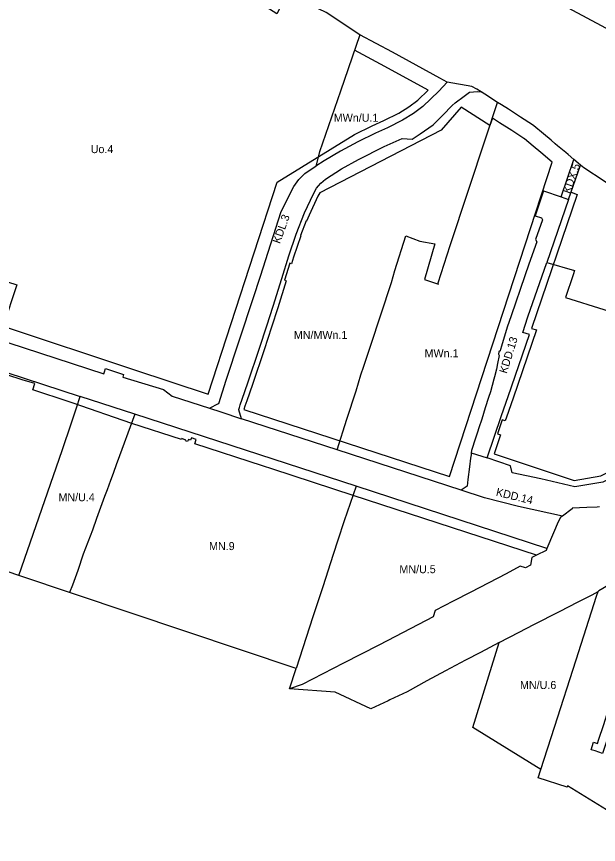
# Model space of a CAD drawing. Extents: x 7416797 to 7419013, y 5549660 to 5551534.
# Drawn here: x 7417878 to 7418242, y 5549927 to 5550444 of the extents above; entities that cross this region are included whole.
import ezdxf

# ---------------------------------------------------------------- set-up
doc = ezdxf.new("R2010")
doc.units = 0
for name, color, linetype in [('LIN_Linia Zabudowy Nieprzekraczalna', 7, 'Continuous'), ('LIN_linie_rozgraniczajace', 7, 'Continuous'), ('TXT_Oznaczenia_przeznaczen', 7, 'Continuous')]:
    doc.layers.add(name, color=color, linetype=linetype)

msp = doc.modelspace()

# ---------------------------------------------------------------- linework, layer by layer
at = {"layer": 'LIN_Linia Zabudowy Nieprzekraczalna'}
msp.add_line((7418173.82, 5550375.74), (7418155.85, 5550387.25), dxfattribs=at)
for points in [[(7417840.12, 5550288.54), (7417878.46, 5550276.31), (7417869.88, 5550250.33), (7417951.32, 5550223.45), (7417997.93, 5550208.07), (7418041.12, 5550340.32), (7418089.34, 5550370.12), (7418100.28, 5550375.53), (7418107.68, 5550378.78), (7418116.88, 5550383.37), (7418123.2, 5550387.43), (7418128.8, 5550391.54), (7418135.37, 5550397.89), (7418108.17, 5550412.67), (7418089.38, 5550422.85)], [(7418155.85, 5550387.25), (7418143.37, 5550372.91), (7418067.56, 5550333.64), (7418066.5, 5550331.51), (7418060.9, 5550319.78), (7418059.42, 5550316.03), (7418059.04, 5550316.17), (7418055.57, 5550306.95), (7418055.82, 5550306.86), (7418051.29, 5550293.44), (7418050.02, 5550289.37), (7418048.88, 5550289.73), (7418045.51, 5550279.16), (7418046.72, 5550278.77), (7418041.43, 5550261.95), (7418037.57, 5550249.74), (7418032.89, 5550235.73), (7418025.56, 5550214), (7418022.12, 5550203.89), (7418020.92, 5550200.38), (7418020.3, 5550198.47), (7418148.65, 5550156.5), (7418212.68, 5550352.85)], [(7418212.68, 5550352.85), (7418205.54, 5550358.86), (7418200.77, 5550362.87), (7418195.35, 5550367.43), (7418195.01, 5550367.64), (7418187.44, 5550372.56), (7418179.91, 5550377.45), (7418175.37, 5550380.38), (7418173.82, 5550375.74)], [(7418224.51, 5550334.02), (7418228.27, 5550332.74), (7418199.84, 5550249.04), (7418202.92, 5550248.15), (7418188.27, 5550205.44), (7418184.09, 5550193.56), (7418183.3, 5550191.24), (7418181.39, 5550191.86), (7418178.51, 5550183.17), (7418180.35, 5550182.52), (7418176.38, 5550170.79)], [(7418176.38, 5550170.79), (7418226.4, 5550154.02), (7418242.97, 5550156.96), (7418327.21, 5550199.31), (7418361.69, 5550210.89), (7418382.5, 5550273.76)], [(7418202.86, 5550107.48), (7418088.49, 5550144.72), (7418038.24, 5550161.14), (7418031.79, 5550163.31), (7417989.56, 5550177), (7417990.47, 5550179.64), (7417987.45, 5550180.72), (7417986.89, 5550179.22), (7417985.65, 5550179.68), (7417985.14, 5550178.4), (7417983.81, 5550178.86), (7417983.97, 5550179.27), (7417981.48, 5550180.23), (7417981.26, 5550179.68), (7417950.32, 5550189.71), (7417913.08, 5550202.54), (7417904.24, 5550205.44), (7417895.44, 5550208.37), (7417888.52, 5550210.72), (7417889.7, 5550214.55), (7417881.87, 5550216.96), (7417872.29, 5550220.12), (7417870.86, 5550215.59), (7417858.1, 5550219.74)]]:
    msp.add_lwpolyline(points, dxfattribs=at)
at = {"layer": 'LIN_linie_rozgraniczajace'}
for p, q in [((7418218.23, 5550331.16), (7418226.3, 5550354.48)), ((7418059.79, 5550346.72), (7418065.2, 5550350.32)), ((7418222.96, 5550329.55), (7418230.4, 5550351.03)), ((7417952.19, 5550195.41), (7417917.95, 5550206.56)), ((7418090.35, 5550150.42), (7417952.19, 5550195.41)), ((7418155.91, 5550148), (7418078.49, 5550173.21)), ((7418162.19, 5550171.4), (7418172.05, 5550168.19)), ((7418209.39, 5550111.66), (7418090.35, 5550150.42))]:
    msp.add_line(p, q, dxfattribs=at)
for points in [[(7418092.7, 5550432.42), (7418071.51, 5550446.22), (7418057.57, 5550452.93), (7418047.73, 5550458.5), (7418040.72, 5550445.49), (7417999.52, 5550471.94), (7418014.05, 5550489.79), (7417968.97, 5550532.54), (7417954.56, 5550547.11), (7417895.48, 5550596.2), (7417893.88, 5550597.78), (7417876.89, 5550604.46), (7417876.86, 5550604.47), (7417873.74, 5550605.53)], [(7418216.45, 5550452.52), (7418293.85, 5550411.16), (7418364.15, 5550380.58), (7418425.56, 5550356.68), (7418460.75, 5550342.97), (7418587.07, 5550302.96), (7418652.56, 5550283.78)], [(7418092.7, 5550432.42), (7418080.49, 5550397.2), (7418067.44, 5550359.23), (7418065.2, 5550350.32)], [(7418147.15, 5550402.87), (7418142.55, 5550405.37), (7418112.94, 5550421.46), (7418092.7, 5550432.42)], [(7418147.15, 5550402.87), (7418141.87, 5550397.2), (7418132.03, 5550387.7), (7418126.03, 5550383.31), (7418119.36, 5550379.02), (7418109.8, 5550374.25), (7418102.39, 5550371), (7418091.42, 5550365.57), (7418080.6, 5550359.71), (7418070.38, 5550353.75), (7418065.2, 5550350.32)], [(7418168.42, 5550396.8), (7418165.58, 5550398.4), (7418162.53, 5550400.12), (7418147.15, 5550402.87)], [(7418018.75, 5550192.67), (7418017.04, 5550198.21), (7418017.01, 5550198.3), (7418017.46, 5550199.73), (7418018, 5550201.39), (7418019.21, 5550204.93), (7418022.65, 5550215.03), (7418029.98, 5550236.75), (7418034.64, 5550250.72), (7418038.49, 5550262.9), (7418043.96, 5550280.27), (7418048.36, 5550294.42), (7418052.93, 5550307.94), (7418058.1, 5550321.13), (7418063.78, 5550333), (7418065.57, 5550336.6), (7418066.77, 5550337.99), (7418068.19, 5550339.65), (7418071.15, 5550342.31), (7418081.09, 5550348.65), (7418091.81, 5550354.49), (7418107.91, 5550362.61), (7418119.15, 5550367.58), (7418125.34, 5550367.29), (7418130.38, 5550370.57), (7418138.38, 5550376.16), (7418144.35, 5550382.16), (7418150.36, 5550388.29), (7418152.05, 5550389.93), (7418157.65, 5550394.05), (7418161.1, 5550396.59), (7418166.07, 5550396.95), (7418168.42, 5550396.8)], [(7418178.64, 5550390.18), (7418170.66, 5550395.35), (7418168.42, 5550396.8)], [(7418078.49, 5550173.21), (7418084.51, 5550192.3), (7418090.24, 5550210.04), (7418093.25, 5550219.94), (7418095.11, 5550225.49), (7418099.22, 5550237.97), (7418112.37, 5550277.66), (7418114.48, 5550285.19), (7418121.37, 5550306.79), (7418130.13, 5550303.54), (7418139.46, 5550301.81), (7418132.9, 5550279.6), (7418141.64, 5550276.56), (7418141.42, 5550277.44), (7418149.01, 5550300.79), (7418171.47, 5550368.72), (7418178.64, 5550390.18)], [(7418226.3, 5550354.48), (7418222.58, 5550357.61), (7418221.15, 5550358.81), (7418217.06, 5550362.24), (7418216.03, 5550363.11), (7418214.61, 5550364.3), (7418211.97, 5550366.52), (7418207.2, 5550370.52), (7418201.29, 5550375.5), (7418200.43, 5550376.05), (7418192.88, 5550380.95), (7418185.34, 5550385.84), (7418180.96, 5550388.67), (7418178.64, 5550390.18)], [(7418230.4, 5550351.03), (7418226.3, 5550354.48)], [(7418392.15, 5550266.3), (7418392.28, 5550269.21), (7418382.5, 5550273.76), (7418363.87, 5550282.44), (7418355.95, 5550286.12), (7418348.45, 5550289.62), (7418339.49, 5550293.79), (7418331.21, 5550297.64), (7418322.84, 5550301.53), (7418313.92, 5550305.69), (7418312.96, 5550306.14), (7418304.3, 5550310.28), (7418302.75, 5550310.89), (7418295.33, 5550314.34), (7418285.69, 5550318.83), (7418283.2, 5550319.99), (7418270, 5550326.12), (7418261.14, 5550330.25), (7418253.52, 5550335.3), (7418245.06, 5550340.92), (7418232.56, 5550349.21), (7418230.4, 5550351.03)], [(7418050.59, 5550336.14), (7418051.44, 5550337.68), (7418052.4, 5550339.17), (7418053.44, 5550340.6), (7418054.56, 5550341.98), (7418055.77, 5550343.28), (7418057.05, 5550344.51), (7418058.39, 5550345.66), (7418059.79, 5550346.72)], [(7417998.7, 5550199.2), (7418004.43, 5550202.1), (7418004.55, 5550202.17), (7418009.28, 5550216.79), (7418025.97, 5550267.77), (7418030.52, 5550281.68), (7418043.5, 5550321.94), (7418050.34, 5550335.66)], [(7418050.34, 5550335.66), (7418050.59, 5550336.14)], [(7418207.37, 5550334.88), (7418202.02, 5550319.37), (7418205.94, 5550318.02), (7418206.56, 5550316.75), (7418202.34, 5550304.54), (7418203.02, 5550303.14), (7418198.18, 5550289.11), (7418195.7, 5550281.91), (7418187.07, 5550256.91), (7418184.62, 5550249.82), (7418181.01, 5550237.9), (7418180.48, 5550235.79), (7418180.29, 5550235.04), (7418179.46, 5550234.47), (7418179.11, 5550233.01), (7418179.63, 5550232.17), (7418178.6, 5550227.15), (7418177.94, 5550223.49), (7418176.66, 5550218.83), (7418176.27, 5550217.43), (7418174.09, 5550209.53), (7418173.04, 5550205.95), (7418170.92, 5550199.35), (7418168.68, 5550192.38), (7418166.9, 5550186.86), (7418166.07, 5550184.29), (7418164.43, 5550179.16), (7418162.74, 5550173.94), (7418162.35, 5550172.72), (7418162.19, 5550171.4)], [(7418207.37, 5550334.88), (7418218.23, 5550331.16)], [(7418222.96, 5550329.55), (7418209.31, 5550290.14)], [(7418218.23, 5550331.16), (7418222.96, 5550329.55)], [(7418172.05, 5550168.19), (7418181.01, 5550194.66), (7418185.19, 5550206.55), (7418198.48, 5550245.27), (7418194.31, 5550246.48), (7418197.6, 5550256.33), (7418209.31, 5550290.14)], [(7418209.31, 5550290.14), (7418226.55, 5550285.12), (7418225.73, 5550282.58), (7418221.11, 5550268.3), (7418292.87, 5550245.8), (7418320.28, 5550237.08), (7418377.67, 5550219.01)], [(7417773.52, 5550271.33), (7417853.01, 5550246.64), (7417932.88, 5550220.63), (7417933.29, 5550221.97), (7417933.89, 5550223.94), (7417945.13, 5550220.23), (7417944.62, 5550218.54), (7417969.99, 5550210.96), (7417975.48, 5550206.76), (7417998.7, 5550199.2)], [(7417859.9, 5550225.47), (7417917.95, 5550206.56)], [(7418375.43, 5550212.39), (7418360.4, 5550206.99), (7418328.79, 5550195.63), (7418244.25, 5550153.12), (7418226.9, 5550150.05), (7418205.6, 5550155.1), (7418187.63, 5550158.95), (7418186.67, 5550163.27), (7418172.05, 5550168.19)], [(7417879.77, 5550094.76), (7417906.89, 5550172.8), (7417912.64, 5550190.06), (7417915.74, 5550199.52), (7417917.95, 5550206.56)], [(7417998.7, 5550199.2), (7418005.83, 5550196.87), (7418018.75, 5550192.67)], [(7417952.19, 5550195.41), (7417941.12, 5550165.41), (7417940.75, 5550164.37), (7417938.62, 5550158.44), (7417937.07, 5550154.12), (7417934.97, 5550148.2), (7417933.33, 5550144.07), (7417928.22, 5550130.23), (7417925.67, 5550123.07), (7417919.84, 5550108.08), (7417916.55, 5550097.85), (7417913.21, 5550088.79), (7417911.47, 5550084.11)], [(7418078.49, 5550173.21), (7418018.75, 5550192.67)], [(7418162.19, 5550171.4), (7418162.02, 5550170.08), (7418161.77, 5550168.09), (7418161.09, 5550162.68), (7418160.08, 5550154.61), (7418159.55, 5550150.42), (7418155.91, 5550148)], [(7418281.81, 5549926.8), (7418222.22, 5549963.42), (7418221.96, 5549962.64), (7418204.05, 5549968.49), (7418205.7, 5549973.58), (7418163.13, 5549999.74), (7418179.57, 5550052.94), (7418167.86, 5550046.74), (7418158.62, 5550041.83), (7418146.2, 5550035.24), (7418134.45, 5550029.01), (7418122.22, 5550022.14), (7418111.37, 5550017.01), (7418110.37, 5550016.54), (7418099.58, 5550011.42), (7418077.2, 5550021.94), (7418048.77, 5550023.87), (7418052.9, 5550036.6), (7417879.77, 5550094.76), (7417692.43, 5550159.1)], [(7418090.35, 5550150.42), (7418082.88, 5550128.81), (7418078.84, 5550116.74), (7418076.07, 5550107.78), (7418069.59, 5550087.61), (7418063.38, 5550068.95), (7418052.9, 5550036.6)], [(7418219.12, 5550131.83), (7418191.75, 5550137.91), (7418170.41, 5550143.28), (7418155.91, 5550148)], [(7418242.31, 5550137.6), (7418240.7, 5550137.5), (7418234.25, 5550137.21), (7418229.79, 5550136.93), (7418225.26, 5550136.77), (7418225.09, 5550136.27), (7418219.12, 5550131.83)], [(7418219.12, 5550131.83), (7418217.97, 5550130.97), (7418216.53, 5550128.27), (7418210, 5550113.08), (7418209.39, 5550111.66)], [(7418209.39, 5550111.66), (7418208.86, 5550110.45), (7418202.86, 5550107.48), (7418199.93, 5550106.02), (7418199.09, 5550101.19), (7418195.96, 5550099.57), (7418192.64, 5550100.54), (7418183.87, 5550095.77), (7418161.99, 5550084.38), (7418150.93, 5550078.71), (7418139.72, 5550072.96), (7418138.43, 5550068.93), (7418114.82, 5550056.71), (7418104.41, 5550051.31), (7418082.43, 5550039.94), (7418056.68, 5550026.59), (7418048.77, 5550023.87)], [(7418258.27, 5550090.51), (7418255.37, 5550090.95), (7418254.21, 5550087.12), (7418247.85, 5550088.77), (7418241.83, 5550085.15), (7418241.32, 5550084.85)], [(7418179.57, 5550052.94), (7418192.07, 5550059.35), (7418201.32, 5550064.1), (7418217.27, 5550072.26), (7418228.97, 5550078.22), (7418237.65, 5550082.64), (7418241.32, 5550084.85)], [(7418205.7, 5549973.58), (7418214.24, 5549999.95), (7418227.68, 5550042.02), (7418240.35, 5550081.8), (7418241.32, 5550084.85)], [(7418279.79, 5550085.49), (7418276.77, 5550083.41), (7418273.95, 5550074.86), (7418265.8, 5550050.2), (7418259.95, 5550032.09), (7418254.13, 5550014.04), (7418244.19, 5549983.62), (7418239.43, 5549985.16), (7418237.02, 5549985.94), (7418238.57, 5549990.7), (7418240.94, 5549989.93), (7418241.74, 5549992.44), (7418244.73, 5550001.12), (7418249.36, 5550015.57), (7418251.63, 5550022.67), (7418255.52, 5550034.79), (7418260.59, 5550050.4), (7418261.66, 5550053.58), (7418262.49, 5550056.06), (7418269.2, 5550076.38), (7418272.04, 5550085), (7418270.92, 5550088.36)]]:
    msp.add_lwpolyline(points, dxfattribs=at)

# ---------------------------------------------------------------- texts
at = {"layer": 'TXT_Oznaczenia_przeznaczen'}
for s, p in [('MWn/U.1', (7418076.35, 5550378.09)), ('Uo.4', (7417924.62, 5550358.5)), ('MN/MWn.1', (7418051.42, 5550242.44)), ('MWn.1', (7418133.05, 5550231.01)), ('MN/U.4', (7417904.49, 5550141.11)), ('MN.9', (7417998.5, 5550110.61)), ('MN/U.5', (7418117.32, 5550096.18)), ('MN/U.6', (7418192.61, 5550023.85))]:
    msp.add_text(s, height=5, dxfattribs=at).set_placement(p)
for s, rotation, p in [('KDX.5', 70.2774, (7418223.82, 5550332.77)), ('KDL.3', 70.2774, (7418042.71, 5550301.57)), ('KDD.13', 72.7589, (7418184.31, 5550220.5)), ('KDD.14', 346.3761, (7418177.28, 5550144.65))]:
    msp.add_text(s, height=5, rotation=rotation, dxfattribs=at).set_placement(p)

doc.saveas('drawing.dxf')
